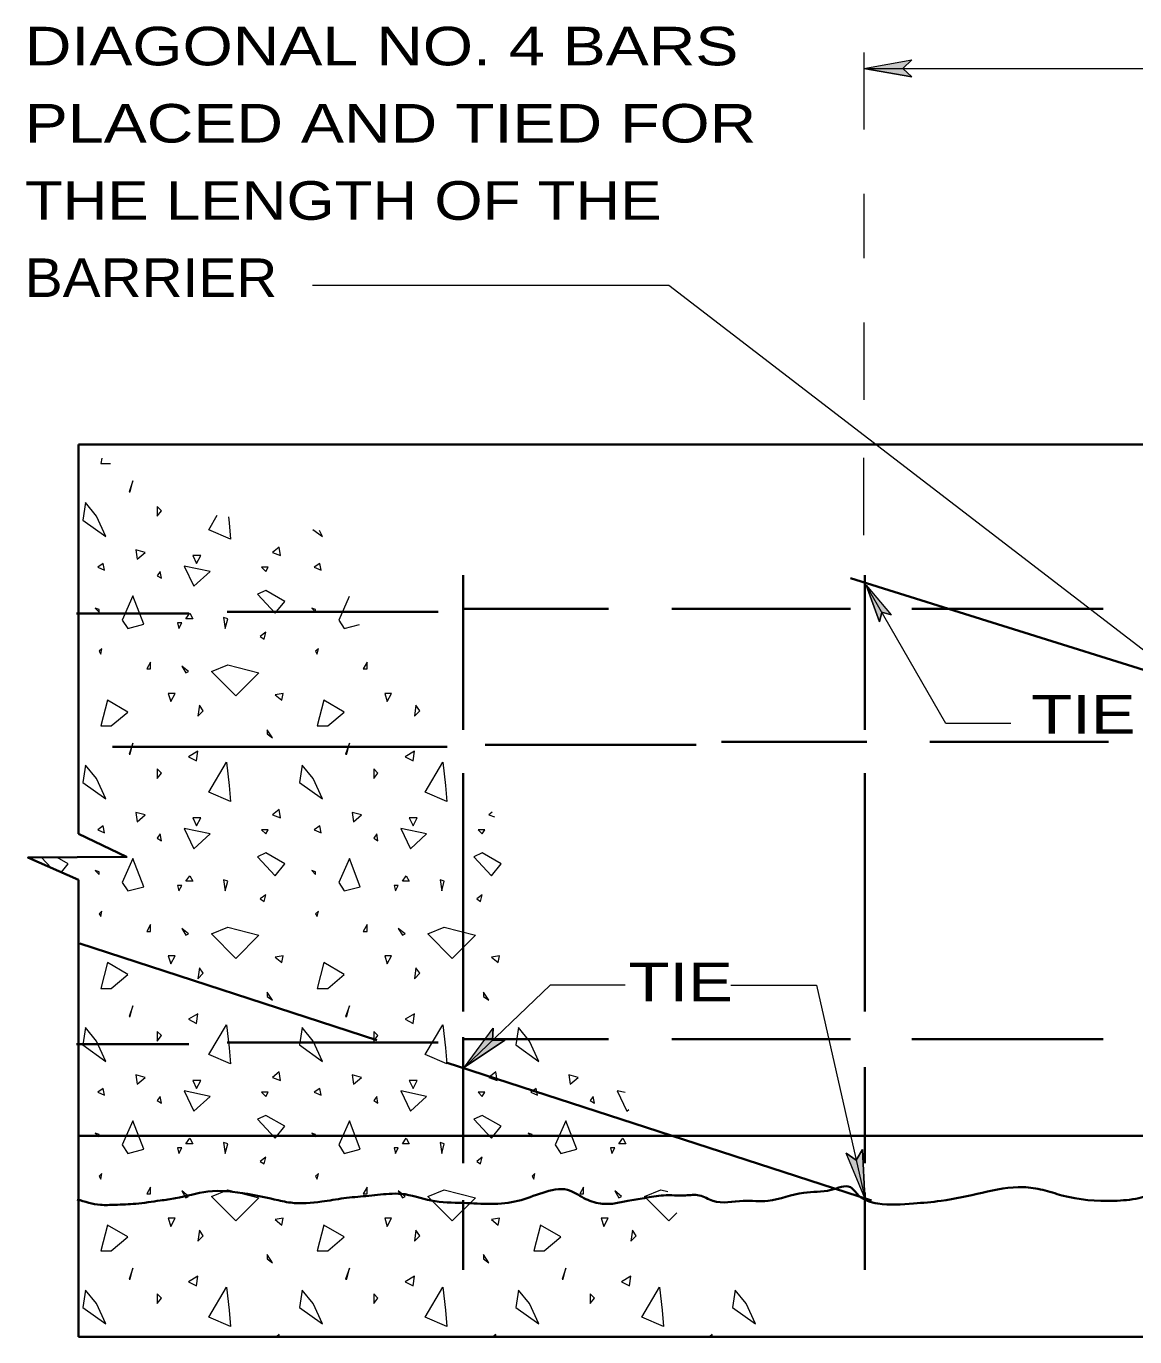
# Model space of a CAD drawing. Extents: x -111.57 to -104.56, y -202.94 to -194.51.
# Drawn here: x -111.574 to -109.851, y -197.16 to -195.123 of the extents above; entities that cross this region are included whole.
import ezdxf

# ---------------------------------------------------------------- set-up
doc = ezdxf.new("R2010")
doc.units = 0
doc.header["$LTSCALE"] = 0.024
doc.linetypes.add('DOT_DASHED', pattern=[7.7, 5, -1.2, 0.3, -1.2])
for name, color, linetype, lineweight in [('1', 7, 'Continuous', 35), ('10', 7, 'Continuous', 13), ('12', 7, 'Continuous', 53), ('6', 7, 'Continuous', 13)]:
    doc.layers.add(name, color=color, linetype=linetype, lineweight=lineweight)

msp = doc.modelspace()

# ---------------------------------------------------------------- hatches: boundary and pattern name
at = {"layer": '10'}
for points in [[(-110.1975, -195.20133), (-110.272, -195.18817), (-110.1975, -195.175), (-110.21167, -195.18817)], [(-110.24783, -196.04817), (-110.26833, -195.99117), (-110.2295, -196.03767), (-110.24433, -196.03317)], [(-110.83017, -196.69867), (-110.893, -196.74067), (-110.84817, -196.67983), (-110.84933, -196.699)], [(-110.27433, -196.86867), (-110.2705, -196.94417), (-110.29983, -196.8745), (-110.284, -196.88533)]]:
    msp.add_hatch(color=256, dxfattribs=at).paths.add_polyline_path(points)

# ---------------------------------------------------------------- linework, layer by layer
at = {"layer": '1'}
for p, q in [((-106.9415, -195.77267), (-111.493, -195.77267)), ((-110.89483, -195.976), (-110.89483, -196.2165)), ((-110.29317, -195.98067), (-109.73333, -196.156)), ((-110.27067, -195.976), (-110.27067, -196.2165)), ((-110.89483, -196.028), (-110.66883, -196.028)), ((-110.29317, -196.028), (-110.57067, -196.028)), ((-109.90033, -196.028), (-110.19783, -196.028)), ((-111.496, -196.0355), (-111.32117, -196.0355)), ((-111.26183, -196.03283), (-110.93383, -196.03283)), ((-111.44017, -196.2425), (-110.92, -196.2425)), ((-110.8605, -196.23983), (-110.53267, -196.23983)), ((-110.4935, -196.235), (-110.26767, -196.235)), ((-109.89183, -196.235), (-110.1695, -196.235)), ((-110.89483, -196.28383), (-110.89483, -196.65417)), ((-110.27067, -196.28383), (-110.27067, -196.65417)), ((-111.49083, -196.54833), (-111.02917, -196.6985)), ((-110.89483, -196.694), (-110.89483, -196.89)), ((-110.89483, -196.69733), (-110.66883, -196.69733)), ((-110.29317, -196.69733), (-110.57067, -196.69733)), ((-109.90033, -196.69733), (-110.19783, -196.69733)), ((-111.496, -196.705), (-111.32117, -196.705)), ((-111.26183, -196.70217), (-110.93383, -196.70217)), ((-110.2605, -196.94817), (-110.9215, -196.7335)), ((-110.27067, -196.74083), (-110.27067, -196.89)), ((-106.9415, -196.84767), (-111.493, -196.84767)), ((-110.27067, -197.05567), (-110.27067, -196.93533)), ((-110.89483, -197.05567), (-110.89483, -196.94767))]:
    msp.add_line(p, q, dxfattribs=at)
msp.add_lwpolyline([(-106.9415, -195.77267), (-106.9415, -197.15983), (-111.493, -197.15983)], dxfattribs=at)
for points in [[(-110.89483, -196.95167), (-110.80983, -196.9485), (-110.77133, -196.93583), (-110.73283, -196.9315), (-110.70733, -196.94417), (-110.68167, -196.95267), (-110.66033, -196.95267), (-110.639, -196.9485), (-110.61333, -196.94417), (-110.5835, -196.94), (-110.54933, -196.94), (-110.528, -196.94), (-110.50667, -196.9485), (-110.45967, -196.9485), (-110.42117, -196.9485), (-110.36567, -196.93583), (-110.323, -196.9315), (-110.29317, -196.92717), (-110.28033, -196.94), (-110.2505, -196.95267), (-110.19483, -196.95267), (-110.15217, -196.9485), (-110.08817, -196.93583), (-110.02417, -196.92717), (-109.99417, -196.9315), (-109.96433, -196.94), (-109.88317, -196.9485), (-109.84483, -196.94417), (-109.81483, -196.93583), (-109.768, -196.92717), (-109.704, -196.923), (-109.67817, -196.92717), (-109.6185, -196.93583), (-109.56717, -196.94417), (-109.49033, -196.9485), (-109.42633, -196.95267), (-109.34517, -196.94417), (-109.28967, -196.94417), (-109.22567, -196.9315), (-109.1615, -196.923), (-109.11033, -196.923), (-109.02067, -196.93583), (-108.93533, -196.94417), (-108.8585, -196.9485), (-108.773, -196.9485), (-108.70467, -196.9485), (-108.615, -196.94), (-108.52967, -196.92717), (-108.46133, -196.9145), (-108.376, -196.9315), (-108.30767, -196.94), (-108.21783, -196.94417), (-108.1155, -196.94), (-108.03433, -196.93583), (-107.966, -196.9315), (-107.902, -196.92717), (-107.82083, -196.91867), (-107.76533, -196.92717), (-107.71833, -196.93583), (-107.63717, -196.94417), (-107.54333, -196.94), (-107.50483, -196.9315), (-107.45367, -196.923), (-107.411, -196.923), (-107.31267, -196.9315), (-107.23583, -196.94417), (-107.159, -196.96117), (-107.03517, -196.96117), (-106.9415, -196.95167)], [(-110.89483, -196.95167), (-110.9445, -196.948), (-110.991, -196.93767), (-111.00983, -196.93767), (-111.046, -196.941), (-111.08033, -196.9445), (-111.11483, -196.94967), (-111.163, -196.95133), (-111.18867, -196.94617), (-111.23, -196.93767), (-111.292, -196.93417), (-111.34183, -196.9445), (-111.36583, -196.948), (-111.40367, -196.953), (-111.43633, -196.95467), (-111.45867, -196.95467), (-111.49483, -196.94617)]]:
    msp.add_spline(points, degree=3, dxfattribs=at)
at = {"layer": '10', "linetype": 'DOT_DASHED'}
for p, q in [((-110.272, -195.16317), (-110.272, -195.7395)), ((-110.272, -195.9135), (-110.272, -195.79033))]:
    msp.add_line(p, q, dxfattribs=at)
at = {"layer": '10'}
for p, q in [((-110.272, -195.18817), (-110.1975, -195.175)), ((-110.272, -195.18817), (-107.1465, -195.18817)), ((-110.272, -195.18817), (-110.1975, -195.20133)), ((-110.145, -196.2065), (-110.26833, -195.99117)), ((-110.26833, -195.99117), (-110.24783, -196.04817)), ((-110.26833, -195.99117), (-110.2295, -196.03767)), ((-110.04367, -196.2065), (-110.145, -196.2065)), ((-110.47867, -196.61333), (-110.34583, -196.61333)), ((-110.34583, -196.61333), (-110.2705, -196.94417)), ((-110.893, -196.74067), (-110.84817, -196.67983)), ((-110.893, -196.74067), (-110.83017, -196.69867)), ((-110.2705, -196.94417), (-110.29983, -196.8745)), ((-110.2705, -196.94417), (-110.27433, -196.86867))]:
    msp.add_line(p, q, dxfattribs=at)
at = {"layer": '10', "lineweight": 35}
for p, q in [((-111.493, -195.77267), (-111.493, -196.37817)), ((-111.493, -197.15983), (-111.493, -196.44933))]:
    msp.add_line(p, q, dxfattribs=at)
at = {"layer": '10'}
for points in [[(-110.1975, -195.20133), (-110.272, -195.18817), (-110.1975, -195.175), (-110.21167, -195.18817)], [(-110.24783, -196.04817), (-110.26833, -195.99117), (-110.2295, -196.03767), (-110.24433, -196.03317)], [(-110.83017, -196.69867), (-110.893, -196.74067), (-110.84817, -196.67983), (-110.84933, -196.699)], [(-110.27433, -196.86867), (-110.2705, -196.94417), (-110.29983, -196.8745), (-110.284, -196.88533)]]:
    msp.add_lwpolyline(points, close=True, dxfattribs=at)
for points in [[(-110.1975, -195.20133), (-110.21167, -195.18817), (-110.1975, -195.175)], [(-111.129, -195.525), (-110.5755, -195.525), (-109.77033, -196.14383)], [(-110.24783, -196.04817), (-110.24433, -196.03317), (-110.2295, -196.03767)], [(-110.643, -196.61333), (-110.75967, -196.61333), (-110.893, -196.74067)], [(-110.83017, -196.69867), (-110.84933, -196.699), (-110.84817, -196.67983)], [(-110.27433, -196.86867), (-110.284, -196.88533), (-110.29983, -196.8745)]]:
    msp.add_lwpolyline(points, dxfattribs=at)
at = {"layer": '10', "lineweight": 35}
msp.add_lwpolyline([(-111.493, -196.44933), (-111.57133, -196.415), (-111.418, -196.41383), (-111.493, -196.37817)], dxfattribs=at)
at = {"layer": '6'}
msp.add_line((-111.55017, -196.41483), (-111.53533, -196.43083), dxfattribs=at)
for points in [[(-111.45633, -195.79417), (-111.45833, -195.80217), (-111.44283, -195.80217)], [(-111.25983, -195.88533), (-111.25883, -195.89467), (-111.25683, -195.91967), (-111.29033, -195.90517), (-111.27717, -195.88283)], [(-111.12883, -195.90483), (-111.11383, -195.91567), (-111.11817, -195.90633)], [(-111.07217, -196.00883), (-111.08833, -196.04567), (-111.07983, -196.05867), (-111.05633, -196.0525)], [(-110.84983, -196.3445), (-110.85483, -196.34867), (-110.8465, -196.35167)], [(-111.5195, -196.43767), (-111.50883, -196.42467), (-111.52617, -196.41467)], [(-110.64317, -196.78017), (-110.65533, -196.77767), (-110.64033, -196.80917), (-110.63733, -196.80633)], [(-110.56283, -196.967), (-110.57533, -196.97967), (-110.61333, -196.94167), (-110.58783, -196.93117), (-110.577, -196.934)], [(-111.18033, -197.15983), (-111.18083, -197.15617), (-111.18533, -197.15983)], [(-110.84383, -197.15983), (-110.84433, -197.15617), (-110.84883, -197.15983)], [(-110.50733, -197.15983), (-110.50783, -197.15617), (-110.51233, -197.15983)]]:
    msp.add_lwpolyline(points, dxfattribs=at)
for points in [[(-111.41433, -195.84617), (-111.41233, -195.84617), (-111.40833, -195.82917)], [(-111.48183, -195.86317), (-111.48583, -195.89017), (-111.45033, -195.91567), (-111.46483, -195.88417)], [(-111.37033, -195.86917), (-111.37033, -195.88417), (-111.36383, -195.87567)], [(-111.40383, -195.93667), (-111.40183, -195.95117), (-111.38933, -195.94067)], [(-111.31533, -195.94517), (-111.30933, -195.95767), (-111.30283, -195.94517)], [(-111.18083, -195.93217), (-111.19133, -195.94067), (-111.17883, -195.94517)], [(-111.46283, -195.96367), (-111.45233, -195.96817), (-111.45433, -195.95767)], [(-111.32833, -195.96167), (-111.31333, -195.99317), (-111.28833, -195.97017)], [(-111.20833, -195.96367), (-111.20183, -195.97017), (-111.19783, -195.96367)], [(-111.12633, -195.96367), (-111.11583, -195.96817), (-111.11783, -195.95767)], [(-111.37033, -195.97667), (-111.36383, -195.98067), (-111.36583, -195.97017)], [(-111.41633, -196.05867), (-111.39133, -196.05217), (-111.40833, -196.00817), (-111.42483, -196.04567)], [(-111.21483, -196.00567), (-111.18733, -196.03517), (-111.17233, -196.01667), (-111.20183, -195.99967)], [(-111.46083, -196.02917), (-111.46683, -196.02717), (-111.46083, -196.03317)], [(-111.12433, -196.02917), (-111.13033, -196.02717), (-111.12433, -196.03317)], [(-111.31983, -196.03517), (-111.31533, -196.04367), (-111.32583, -196.04367)], [(-111.26733, -196.04167), (-111.26483, -196.05867), (-111.26083, -196.04367)], [(-111.33883, -196.05017), (-111.33683, -196.05867), (-111.33233, -196.05017)], [(-111.21033, -196.07117), (-111.20433, -196.07517), (-111.20183, -196.06467)], [(-111.45633, -196.09017), (-111.46083, -196.09417), (-111.45833, -196.09867)], [(-111.11983, -196.09017), (-111.12433, -196.09417), (-111.12183, -196.09867)], [(-111.38083, -196.11117), (-111.38683, -196.12167), (-111.38083, -196.12167)], [(-111.32583, -196.12767), (-111.32183, -196.12567), (-111.33233, -196.11717)], [(-111.26083, -196.11517), (-111.21233, -196.12767), (-111.24833, -196.16367), (-111.28633, -196.12567)], [(-111.04433, -196.11117), (-111.05033, -196.12167), (-111.04433, -196.12167)], [(-111.44183, -196.21017), (-111.41633, -196.18867), (-111.44783, -196.17017), (-111.45833, -196.21017)], [(-111.35333, -196.15967), (-111.34933, -196.17217), (-111.34283, -196.15967)], [(-111.18733, -196.16167), (-111.17683, -196.17017), (-111.17483, -196.15967)], [(-111.10533, -196.21017), (-111.07983, -196.18867), (-111.11133, -196.17017), (-111.12183, -196.21017)], [(-111.01683, -196.15967), (-111.01283, -196.17217), (-111.00633, -196.15967)], [(-111.30483, -196.17817), (-111.30733, -196.19517), (-111.29883, -196.18667)], [(-110.96833, -196.17817), (-110.97083, -196.19517), (-110.96233, -196.18667)], [(-111.19983, -196.21617), (-111.19983, -196.22267), (-111.19133, -196.22867)], [(-111.41433, -196.25417), (-111.41233, -196.25417), (-111.40833, -196.23717)], [(-111.32183, -196.25817), (-111.30933, -196.26467), (-111.30733, -196.24967)], [(-111.07783, -196.25417), (-111.07583, -196.25417), (-111.07183, -196.23717)], [(-110.98533, -196.25817), (-110.97283, -196.26467), (-110.97083, -196.24967)], [(-111.48183, -196.27117), (-111.48583, -196.29817), (-111.45033, -196.32367), (-111.46483, -196.29217)], [(-111.25883, -196.30267), (-111.25683, -196.32767), (-111.29033, -196.31317), (-111.26283, -196.26667)], [(-111.14533, -196.27117), (-111.14933, -196.29817), (-111.11383, -196.32367), (-111.12833, -196.29217)], [(-110.92233, -196.30267), (-110.92033, -196.32767), (-110.95383, -196.31317), (-110.92633, -196.26667)], [(-111.37033, -196.27717), (-111.37033, -196.29217), (-111.36383, -196.28367)], [(-111.03383, -196.27717), (-111.03383, -196.29217), (-111.02733, -196.28367)], [(-111.40383, -196.34467), (-111.40183, -196.35917), (-111.38933, -196.34867)], [(-111.31533, -196.35317), (-111.30933, -196.36567), (-111.30283, -196.35317)], [(-111.18083, -196.34017), (-111.19133, -196.34867), (-111.17883, -196.35317)], [(-111.06733, -196.34467), (-111.06533, -196.35917), (-111.05283, -196.34867)], [(-110.97883, -196.35317), (-110.97283, -196.36567), (-110.96633, -196.35317)], [(-111.46283, -196.37167), (-111.45233, -196.37617), (-111.45433, -196.36567)], [(-111.32833, -196.36967), (-111.31333, -196.40117), (-111.28833, -196.37817)], [(-111.20833, -196.37167), (-111.20183, -196.37817), (-111.19783, -196.37167)], [(-111.12633, -196.37167), (-111.11583, -196.37617), (-111.11783, -196.36567)], [(-110.99183, -196.36967), (-110.97683, -196.40117), (-110.95183, -196.37817)], [(-110.87183, -196.37167), (-110.86533, -196.37817), (-110.86133, -196.37167)], [(-111.37033, -196.38467), (-111.36383, -196.38867), (-111.36583, -196.37817)], [(-111.03383, -196.38467), (-111.02733, -196.38867), (-111.02933, -196.37817)], [(-111.41633, -196.46667), (-111.39133, -196.46017), (-111.40833, -196.41617), (-111.42483, -196.45367)], [(-111.21483, -196.41367), (-111.18733, -196.44317), (-111.17233, -196.42467), (-111.20183, -196.40767)], [(-111.07983, -196.46667), (-111.05483, -196.46017), (-111.07183, -196.41617), (-111.08833, -196.45367)], [(-110.87833, -196.41367), (-110.85083, -196.44317), (-110.83583, -196.42467), (-110.86533, -196.40767)], [(-111.46083, -196.43717), (-111.46683, -196.43517), (-111.46083, -196.44117)], [(-111.12433, -196.43717), (-111.13033, -196.43517), (-111.12433, -196.44117)], [(-111.31983, -196.44317), (-111.31533, -196.45167), (-111.32583, -196.45167)], [(-111.26733, -196.44967), (-111.26483, -196.46667), (-111.26083, -196.45167)], [(-110.98333, -196.44317), (-110.97883, -196.45167), (-110.98933, -196.45167)], [(-110.93083, -196.44967), (-110.92833, -196.46667), (-110.92433, -196.45167)], [(-111.33883, -196.45817), (-111.33683, -196.46667), (-111.33233, -196.45817)], [(-111.21033, -196.47917), (-111.20433, -196.48317), (-111.20183, -196.47267)], [(-111.00233, -196.45817), (-111.00033, -196.46667), (-110.99583, -196.45817)], [(-110.87383, -196.47917), (-110.86783, -196.48317), (-110.86533, -196.47267)], [(-111.45633, -196.49817), (-111.46083, -196.50217), (-111.45833, -196.50667)], [(-111.11983, -196.49817), (-111.12433, -196.50217), (-111.12183, -196.50667)], [(-111.38083, -196.51917), (-111.38683, -196.52967), (-111.38083, -196.52967)], [(-111.32583, -196.53567), (-111.32183, -196.53367), (-111.33233, -196.52517)], [(-111.26083, -196.52317), (-111.21233, -196.53567), (-111.24833, -196.57167), (-111.28633, -196.53367)], [(-111.04433, -196.51917), (-111.05033, -196.52967), (-111.04433, -196.52967)], [(-110.98933, -196.53567), (-110.98533, -196.53367), (-110.99583, -196.52517)], [(-110.92433, -196.52317), (-110.87583, -196.53567), (-110.91183, -196.57167), (-110.94983, -196.53367)], [(-111.44183, -196.61817), (-111.41633, -196.59667), (-111.44783, -196.57817), (-111.45833, -196.61817)], [(-111.35333, -196.56767), (-111.34933, -196.58017), (-111.34283, -196.56767)], [(-111.18733, -196.56967), (-111.17683, -196.57817), (-111.17483, -196.56767)], [(-111.10533, -196.61817), (-111.07983, -196.59667), (-111.11133, -196.57817), (-111.12183, -196.61817)], [(-111.01683, -196.56767), (-111.01283, -196.58017), (-111.00633, -196.56767)], [(-110.85083, -196.56967), (-110.84033, -196.57817), (-110.83833, -196.56767)], [(-111.30483, -196.58617), (-111.30733, -196.60317), (-111.29883, -196.59467)], [(-110.96833, -196.58617), (-110.97083, -196.60317), (-110.96233, -196.59467)], [(-111.19983, -196.62417), (-111.19983, -196.63067), (-111.19133, -196.63667)], [(-110.86333, -196.62417), (-110.86333, -196.63067), (-110.85483, -196.63667)], [(-111.41433, -196.66217), (-111.41233, -196.66217), (-111.40833, -196.64517)], [(-111.32183, -196.66617), (-111.30933, -196.67267), (-111.30733, -196.65767)], [(-111.07783, -196.66217), (-111.07583, -196.66217), (-111.07183, -196.64517)], [(-110.98533, -196.66617), (-110.97283, -196.67267), (-110.97083, -196.65767)], [(-111.48183, -196.67917), (-111.48583, -196.70617), (-111.45033, -196.73167), (-111.46483, -196.70017)], [(-111.25883, -196.71067), (-111.25683, -196.73567), (-111.29033, -196.72117), (-111.26283, -196.67467)], [(-111.14533, -196.67917), (-111.14933, -196.70617), (-111.11383, -196.73167), (-111.12833, -196.70017)], [(-110.92233, -196.71067), (-110.92033, -196.73567), (-110.95383, -196.72117), (-110.92633, -196.67467)], [(-110.80883, -196.67917), (-110.81283, -196.70617), (-110.77733, -196.73167), (-110.79183, -196.70017)], [(-111.37033, -196.68517), (-111.37033, -196.70017), (-111.36383, -196.69167)], [(-111.03383, -196.68517), (-111.03383, -196.70017), (-111.02733, -196.69167)], [(-111.40383, -196.75267), (-111.40183, -196.76717), (-111.38933, -196.75667)], [(-111.31533, -196.76117), (-111.30933, -196.77367), (-111.30283, -196.76117)], [(-111.18083, -196.74817), (-111.19133, -196.75667), (-111.17883, -196.76117)], [(-111.06733, -196.75267), (-111.06533, -196.76717), (-111.05283, -196.75667)], [(-110.97883, -196.76117), (-110.97283, -196.77367), (-110.96633, -196.76117)], [(-110.84433, -196.74817), (-110.85483, -196.75667), (-110.84233, -196.76117)], [(-110.73083, -196.75267), (-110.72883, -196.76717), (-110.71633, -196.75667)], [(-111.46283, -196.77967), (-111.45233, -196.78417), (-111.45433, -196.77367)], [(-111.32833, -196.77767), (-111.31333, -196.80917), (-111.28833, -196.78617)], [(-111.20833, -196.77967), (-111.20183, -196.78617), (-111.19783, -196.77967)], [(-111.12633, -196.77967), (-111.11583, -196.78417), (-111.11783, -196.77367)], [(-110.99183, -196.77767), (-110.97683, -196.80917), (-110.95183, -196.78617)], [(-110.87183, -196.77967), (-110.86533, -196.78617), (-110.86133, -196.77967)], [(-110.78983, -196.77967), (-110.77933, -196.78417), (-110.78133, -196.77367)], [(-111.37033, -196.79267), (-111.36383, -196.79667), (-111.36583, -196.78617)], [(-111.03383, -196.79267), (-111.02733, -196.79667), (-111.02933, -196.78617)], [(-110.69733, -196.79267), (-110.69083, -196.79667), (-110.69283, -196.78617)], [(-111.21483, -196.82167), (-111.18733, -196.85117), (-111.17233, -196.83267), (-111.20183, -196.81567)], [(-110.87833, -196.82167), (-110.85083, -196.85117), (-110.83583, -196.83267), (-110.86533, -196.81567)], [(-111.46083, -196.84517), (-111.46683, -196.84317), (-111.46083, -196.84917)], [(-111.41633, -196.87467), (-111.39133, -196.86817), (-111.40833, -196.82417), (-111.42483, -196.86167)], [(-111.12433, -196.84517), (-111.13033, -196.84317), (-111.12433, -196.84917)], [(-111.07983, -196.87467), (-111.05483, -196.86817), (-111.07183, -196.82417), (-111.08833, -196.86167)], [(-110.78783, -196.84517), (-110.79383, -196.84317), (-110.78783, -196.84917)], [(-110.74333, -196.87467), (-110.71833, -196.86817), (-110.73533, -196.82417), (-110.75183, -196.86167)], [(-111.31983, -196.85117), (-111.31533, -196.85967), (-111.32583, -196.85967)], [(-111.26733, -196.85767), (-111.26483, -196.87467), (-111.26083, -196.85967)], [(-110.98333, -196.85117), (-110.97883, -196.85967), (-110.98933, -196.85967)], [(-110.93083, -196.85767), (-110.92833, -196.87467), (-110.92433, -196.85967)], [(-110.64683, -196.85117), (-110.64233, -196.85967), (-110.65283, -196.85967)], [(-111.33883, -196.86617), (-111.33683, -196.87467), (-111.33233, -196.86617)], [(-111.21033, -196.88717), (-111.20433, -196.89117), (-111.20183, -196.88067)], [(-111.00233, -196.86617), (-111.00033, -196.87467), (-110.99583, -196.86617)], [(-110.87383, -196.88717), (-110.86783, -196.89117), (-110.86533, -196.88067)], [(-110.66583, -196.86617), (-110.66383, -196.87467), (-110.65933, -196.86617)], [(-111.45633, -196.90617), (-111.46083, -196.91017), (-111.45833, -196.91467)], [(-111.11983, -196.90617), (-111.12433, -196.91017), (-111.12183, -196.91467)], [(-110.78333, -196.90617), (-110.78783, -196.91017), (-110.78533, -196.91467)], [(-111.38083, -196.92717), (-111.38683, -196.93767), (-111.38083, -196.93767)], [(-111.32583, -196.94367), (-111.32183, -196.94167), (-111.33233, -196.93317)], [(-111.26083, -196.93117), (-111.21233, -196.94367), (-111.24833, -196.97967), (-111.28633, -196.94167)], [(-111.04433, -196.92717), (-111.05033, -196.93767), (-111.04433, -196.93767)], [(-110.98933, -196.94367), (-110.98533, -196.94167), (-110.99583, -196.93317)], [(-110.92433, -196.93117), (-110.87583, -196.94367), (-110.91183, -196.97967), (-110.94983, -196.94167)], [(-110.70783, -196.92717), (-110.71383, -196.93767), (-110.70783, -196.93767)], [(-110.65283, -196.94367), (-110.64883, -196.94167), (-110.65933, -196.93317)], [(-111.44183, -197.02617), (-111.41633, -197.00467), (-111.44783, -196.98617), (-111.45833, -197.02617)], [(-111.35333, -196.97567), (-111.34933, -196.98817), (-111.34283, -196.97567)], [(-111.18733, -196.97767), (-111.17683, -196.98617), (-111.17483, -196.97567)], [(-111.10533, -197.02617), (-111.07983, -197.00467), (-111.11133, -196.98617), (-111.12183, -197.02617)], [(-111.01683, -196.97567), (-111.01283, -196.98817), (-111.00633, -196.97567)], [(-110.85083, -196.97767), (-110.84033, -196.98617), (-110.83833, -196.97567)], [(-110.76883, -197.02617), (-110.74333, -197.00467), (-110.77483, -196.98617), (-110.78533, -197.02617)], [(-110.68033, -196.97567), (-110.67633, -196.98817), (-110.66983, -196.97567)], [(-111.30483, -196.99417), (-111.30733, -197.01117), (-111.29883, -197.00267)], [(-110.96833, -196.99417), (-110.97083, -197.01117), (-110.96233, -197.00267)], [(-110.63183, -196.99417), (-110.63433, -197.01117), (-110.62583, -197.00267)], [(-111.19983, -197.03217), (-111.19983, -197.03867), (-111.19133, -197.04467)], [(-110.86333, -197.03217), (-110.86333, -197.03867), (-110.85483, -197.04467)], [(-111.41433, -197.07017), (-111.41233, -197.07017), (-111.40833, -197.05317)], [(-111.32183, -197.07417), (-111.30933, -197.08067), (-111.30733, -197.06567)], [(-111.07783, -197.07017), (-111.07583, -197.07017), (-111.07183, -197.05317)], [(-110.98533, -197.07417), (-110.97283, -197.08067), (-110.97083, -197.06567)], [(-110.74133, -197.07017), (-110.73933, -197.07017), (-110.73533, -197.05317)], [(-110.64883, -197.07417), (-110.63633, -197.08067), (-110.63433, -197.06567)], [(-111.48183, -197.08717), (-111.48583, -197.11417), (-111.45033, -197.13967), (-111.46483, -197.10817)], [(-111.25883, -197.11867), (-111.25683, -197.14367), (-111.29033, -197.12917), (-111.26283, -197.08267)], [(-111.14533, -197.08717), (-111.14933, -197.11417), (-111.11383, -197.13967), (-111.12833, -197.10817)], [(-110.92233, -197.11867), (-110.92033, -197.14367), (-110.95383, -197.12917), (-110.92633, -197.08267)], [(-110.80883, -197.08717), (-110.81283, -197.11417), (-110.77733, -197.13967), (-110.79183, -197.10817)], [(-110.58583, -197.11867), (-110.58383, -197.14367), (-110.61733, -197.12917), (-110.58983, -197.08267)], [(-110.47233, -197.08717), (-110.47633, -197.11417), (-110.44083, -197.13967), (-110.45533, -197.10817)], [(-111.37033, -197.09317), (-111.37033, -197.10817), (-111.36383, -197.09967)], [(-111.03383, -197.09317), (-111.03383, -197.10817), (-111.02733, -197.09967)], [(-110.69733, -197.09317), (-110.69733, -197.10817), (-110.69083, -197.09967)]]:
    msp.add_lwpolyline(points, close=True, dxfattribs=at)

# ---------------------------------------------------------------- texts
at = {"layer": '12'}
for s, width, p in [('DIAGONAL NO. 4 BARS', 1.25, (-111.57625, -195.18342)), ('PLACED AND TIED FOR', 1.25, (-111.57625, -195.30342)), ('THE LENGTH OF THE', 1.2, (-111.57625, -195.42342)), ('BARRIER', 1.1, (-111.57625, -195.5435)), ('TIE', 1.3, (-110.01192, -196.22233)), ('TIE', 1.3, (-110.63808, -196.6385))]:
    msp.add_text(s, height=0.06, dxfattribs=dict(at, width=width)).set_placement(p)

doc.saveas('drawing.dxf')
